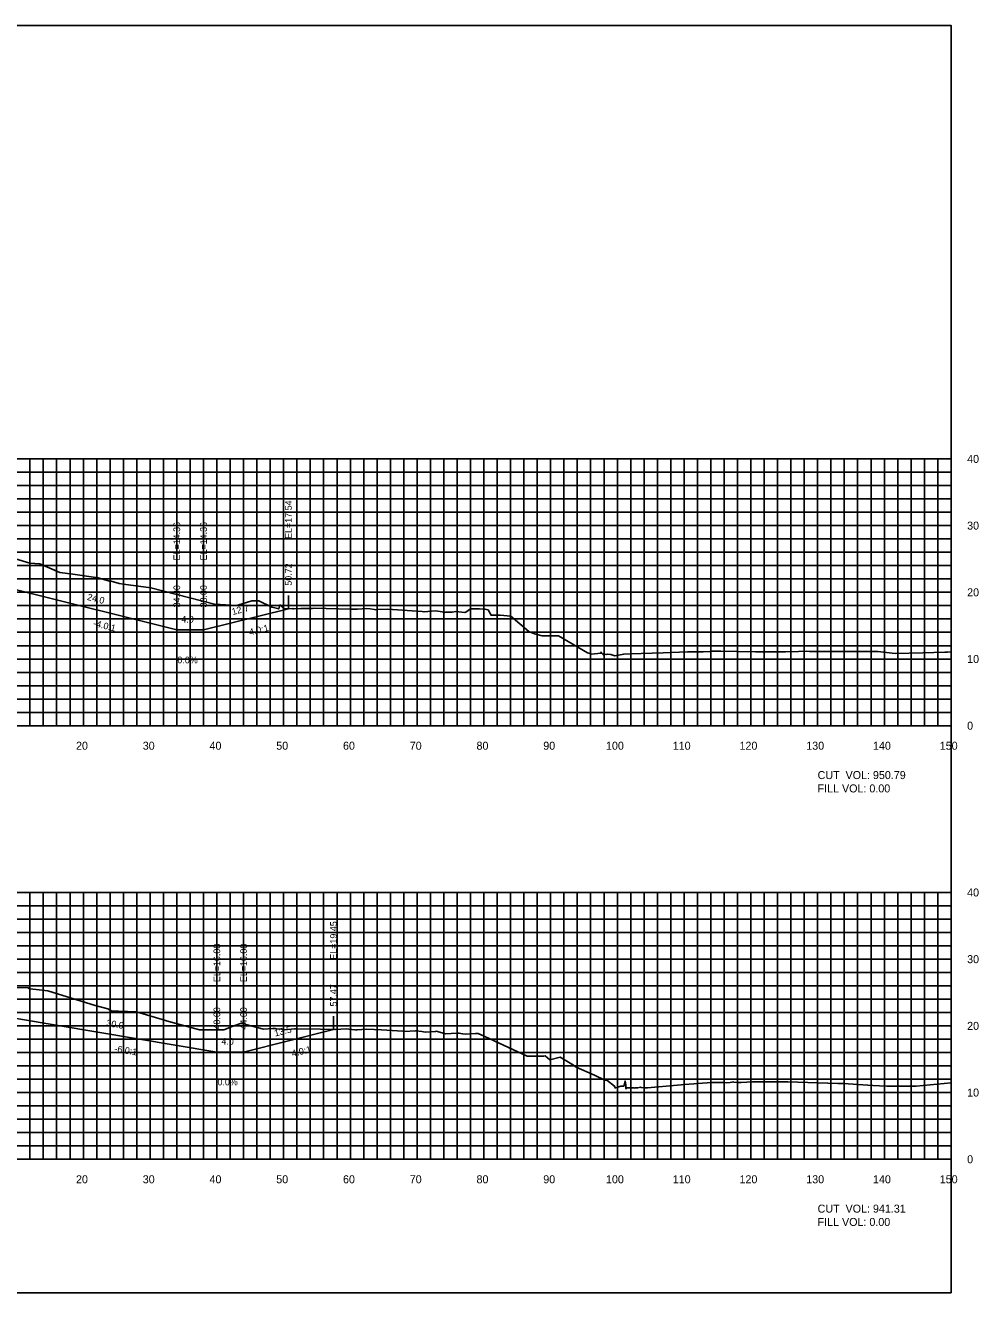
# Model space of a CAD drawing. Extents: x 1800976 to 1805104, y 250057 to 250580.
# Drawn here: x 1803322.3 to 1803465.1, y 250079.4 to 250269.4 of the extents above; entities that cross this region are included whole.
import ezdxf

# ---------------------------------------------------------------- set-up
doc = ezdxf.new("R2010")
doc.units = 0
for name, color, linetype in [('10', 7, 'Continuous'), ('3', 7, 'Continuous'), ('31', 7, 'Continuous'), ('4', 7, 'Continuous'), ('60', 7, 'Continuous'), ('ANNO-TXT', 7, 'Continuous'), ('CL-CNST', 7, 'Continuous'), ('Level 62', 7, 'Continuous'), ('M-ROADS', 7, 'Continuous')]:
    doc.layers.add(name, color=color, linetype=linetype)

msp = doc.modelspace()

# ---------------------------------------------------------------- linework, layer by layer
for p, q in [((1803361.72, 250181.97), (1803361.72, 250183.97)), ((1803345, 250178.79), (1803345, 250180.79)), ((1803349, 250178.79), (1803349, 250180.79)), ((1803368.47, 250118.88), (1803368.47, 250120.88)), ((1803351, 250115.51), (1803351, 250117.51)), ((1803355, 250115.51), (1803355, 250117.51))]:
    msp.add_line(p, q)
msp.add_lwpolyline([(1803161, 250079.43), (1803461, 250079.43), (1803461, 250269.43), (1803161, 250269.43)], close=True)
at = {"layer": '60'}
for p, q in [((1803461, 250164.43), (1803461, 250204.43)), ((1803461.06, 250204.43), (1803461, 250204.43)), ((1803461.06, 250194.43), (1803461, 250194.43)), ((1803461.06, 250184.43), (1803461, 250184.43)), ((1803461.06, 250174.43), (1803461, 250174.43)), ((1803161, 250164.43), (1803461, 250164.43)), ((1803331, 250164.37), (1803331, 250164.43)), ((1803341, 250164.37), (1803341, 250164.43)), ((1803351, 250164.37), (1803351, 250164.43)), ((1803361, 250164.37), (1803361, 250164.43)), ((1803371, 250164.37), (1803371, 250164.43)), ((1803381, 250164.37), (1803381, 250164.43)), ((1803391, 250164.37), (1803391, 250164.43)), ((1803401, 250164.37), (1803401, 250164.43)), ((1803411, 250164.37), (1803411, 250164.43)), ((1803421, 250164.37), (1803421, 250164.43)), ((1803431, 250164.37), (1803431, 250164.43)), ((1803441, 250164.37), (1803441, 250164.43)), ((1803451, 250164.37), (1803451, 250164.43)), ((1803461, 250164.37), (1803461, 250164.43)), ((1803461.06, 250164.43), (1803461, 250164.43)), ((1803461, 250099.43), (1803461, 250139.43)), ((1803461.06, 250139.43), (1803461, 250139.43)), ((1803461.06, 250129.43), (1803461, 250129.43)), ((1803461.06, 250119.43), (1803461, 250119.43)), ((1803461.06, 250109.43), (1803461, 250109.43)), ((1803161, 250099.43), (1803461, 250099.43)), ((1803331, 250099.37), (1803331, 250099.43)), ((1803341, 250099.37), (1803341, 250099.43)), ((1803351, 250099.37), (1803351, 250099.43)), ((1803361, 250099.37), (1803361, 250099.43)), ((1803371, 250099.37), (1803371, 250099.43)), ((1803381, 250099.37), (1803381, 250099.43)), ((1803391, 250099.37), (1803391, 250099.43)), ((1803401, 250099.37), (1803401, 250099.43)), ((1803411, 250099.37), (1803411, 250099.43)), ((1803421, 250099.37), (1803421, 250099.43)), ((1803431, 250099.37), (1803431, 250099.43)), ((1803441, 250099.37), (1803441, 250099.43)), ((1803451, 250099.37), (1803451, 250099.43)), ((1803461, 250099.37), (1803461, 250099.43)), ((1803461.06, 250099.43), (1803461, 250099.43))]:
    msp.add_line(p, q, dxfattribs=at)
at = {"layer": 'CL-CNST'}
for points in [[(1803267.75, 250186.14), (1803275, 250185.98), (1803311, 250185.19), (1803319, 250184.87), (1803321, 250184.79), (1803345, 250178.79), (1803349, 250178.79), (1803361.72, 250181.97)], [(1803268.63, 250120.34), (1803274.63, 250121.34), (1803276.67, 250121.42), (1803280.67, 250121.58), (1803311, 250120.91), (1803319, 250120.59), (1803321, 250120.51), (1803351, 250115.51), (1803355, 250115.51), (1803368.47, 250118.88)]]:
    msp.add_lwpolyline(points, dxfattribs=at)
at = {"layer": 'Level 62'}
for p, q in [((1803161, 250204.43), (1803461, 250204.43)), ((1803323, 250164.43), (1803323, 250204.43)), ((1803325, 250164.43), (1803325, 250204.43)), ((1803327, 250164.43), (1803327, 250204.43)), ((1803329, 250164.43), (1803329, 250204.43)), ((1803331, 250164.43), (1803331, 250204.43)), ((1803333, 250164.43), (1803333, 250204.43)), ((1803335, 250164.43), (1803335, 250204.43)), ((1803337, 250164.43), (1803337, 250204.43)), ((1803339, 250164.43), (1803339, 250204.43)), ((1803341, 250164.43), (1803341, 250204.43)), ((1803343, 250164.43), (1803343, 250204.43)), ((1803345, 250164.43), (1803345, 250204.43)), ((1803347, 250164.43), (1803347, 250204.43)), ((1803349, 250164.43), (1803349, 250204.43)), ((1803351, 250164.43), (1803351, 250204.43)), ((1803353, 250164.43), (1803353, 250204.43)), ((1803355, 250164.43), (1803355, 250204.43)), ((1803357, 250164.43), (1803357, 250204.43)), ((1803359, 250164.43), (1803359, 250204.43)), ((1803361, 250164.43), (1803361, 250204.43)), ((1803363, 250164.43), (1803363, 250204.43)), ((1803365, 250164.43), (1803365, 250204.43)), ((1803367, 250164.43), (1803367, 250204.43)), ((1803369, 250164.43), (1803369, 250204.43)), ((1803371, 250164.43), (1803371, 250204.43)), ((1803373, 250164.43), (1803373, 250204.43)), ((1803375, 250164.43), (1803375, 250204.43)), ((1803377, 250164.43), (1803377, 250204.43)), ((1803379, 250164.43), (1803379, 250204.43)), ((1803381, 250164.43), (1803381, 250204.43)), ((1803383, 250164.43), (1803383, 250204.43)), ((1803385, 250164.43), (1803385, 250204.43)), ((1803387, 250164.43), (1803387, 250204.43)), ((1803389, 250164.43), (1803389, 250204.43)), ((1803391, 250164.43), (1803391, 250204.43)), ((1803393, 250164.43), (1803393, 250204.43)), ((1803395, 250164.43), (1803395, 250204.43)), ((1803397, 250164.43), (1803397, 250204.43)), ((1803399, 250164.43), (1803399, 250204.43)), ((1803401, 250164.43), (1803401, 250204.43)), ((1803403, 250164.43), (1803403, 250204.43)), ((1803405, 250164.43), (1803405, 250204.43)), ((1803407, 250164.43), (1803407, 250204.43)), ((1803409, 250164.43), (1803409, 250204.43)), ((1803411, 250164.43), (1803411, 250204.43)), ((1803413, 250164.43), (1803413, 250204.43)), ((1803415, 250164.43), (1803415, 250204.43)), ((1803417, 250164.43), (1803417, 250204.43)), ((1803419, 250164.43), (1803419, 250204.43)), ((1803421, 250164.43), (1803421, 250204.43)), ((1803423, 250164.43), (1803423, 250204.43)), ((1803425, 250164.43), (1803425, 250204.43)), ((1803427, 250164.43), (1803427, 250204.43)), ((1803429, 250164.43), (1803429, 250204.43)), ((1803431, 250164.43), (1803431, 250204.43)), ((1803433, 250164.43), (1803433, 250204.43)), ((1803435, 250164.43), (1803435, 250204.43)), ((1803437, 250164.43), (1803437, 250204.43)), ((1803439, 250164.43), (1803439, 250204.43)), ((1803441, 250164.43), (1803441, 250204.43)), ((1803443, 250164.43), (1803443, 250204.43)), ((1803445, 250164.43), (1803445, 250204.43)), ((1803447, 250164.43), (1803447, 250204.43)), ((1803449, 250164.43), (1803449, 250204.43)), ((1803451, 250164.43), (1803451, 250204.43)), ((1803453, 250164.43), (1803453, 250204.43)), ((1803455, 250164.43), (1803455, 250204.43)), ((1803457, 250164.43), (1803457, 250204.43)), ((1803459, 250164.43), (1803459, 250204.43)), ((1803461, 250164.43), (1803461, 250204.43)), ((1803161, 250202.43), (1803461, 250202.43)), ((1803161, 250200.43), (1803461, 250200.43)), ((1803161, 250198.43), (1803461, 250198.43)), ((1803161, 250196.43), (1803461, 250196.43)), ((1803161, 250194.43), (1803461, 250194.43)), ((1803161, 250192.43), (1803461, 250192.43)), ((1803161, 250190.43), (1803461, 250190.43)), ((1803161, 250188.43), (1803461, 250188.43)), ((1803161, 250186.43), (1803461, 250186.43)), ((1803161, 250184.43), (1803461, 250184.43)), ((1803161, 250182.43), (1803461, 250182.43)), ((1803161, 250180.43), (1803461, 250180.43)), ((1803161, 250178.43), (1803461, 250178.43)), ((1803161, 250176.43), (1803461, 250176.43)), ((1803161, 250174.43), (1803461, 250174.43)), ((1803161, 250172.43), (1803461, 250172.43)), ((1803161, 250170.43), (1803461, 250170.43)), ((1803161, 250168.43), (1803461, 250168.43)), ((1803161, 250166.43), (1803461, 250166.43)), ((1803161, 250164.43), (1803461, 250164.43)), ((1803161, 250139.43), (1803461, 250139.43)), ((1803323, 250099.43), (1803323, 250139.43)), ((1803325, 250099.43), (1803325, 250139.43)), ((1803327, 250099.43), (1803327, 250139.43)), ((1803329, 250099.43), (1803329, 250139.43)), ((1803331, 250099.43), (1803331, 250139.43)), ((1803333, 250099.43), (1803333, 250139.43)), ((1803335, 250099.43), (1803335, 250139.43)), ((1803337, 250099.43), (1803337, 250139.43)), ((1803339, 250099.43), (1803339, 250139.43)), ((1803341, 250099.43), (1803341, 250139.43)), ((1803343, 250099.43), (1803343, 250139.43)), ((1803345, 250099.43), (1803345, 250139.43)), ((1803347, 250099.43), (1803347, 250139.43)), ((1803349, 250099.43), (1803349, 250139.43)), ((1803351, 250099.43), (1803351, 250139.43)), ((1803353, 250099.43), (1803353, 250139.43)), ((1803355, 250099.43), (1803355, 250139.43)), ((1803357, 250099.43), (1803357, 250139.43)), ((1803359, 250099.43), (1803359, 250139.43)), ((1803361, 250099.43), (1803361, 250139.43)), ((1803363, 250099.43), (1803363, 250139.43)), ((1803365, 250099.43), (1803365, 250139.43)), ((1803367, 250099.43), (1803367, 250139.43)), ((1803369, 250099.43), (1803369, 250139.43)), ((1803371, 250099.43), (1803371, 250139.43)), ((1803373, 250099.43), (1803373, 250139.43)), ((1803375, 250099.43), (1803375, 250139.43)), ((1803377, 250099.43), (1803377, 250139.43)), ((1803379, 250099.43), (1803379, 250139.43)), ((1803381, 250099.43), (1803381, 250139.43)), ((1803383, 250099.43), (1803383, 250139.43)), ((1803385, 250099.43), (1803385, 250139.43)), ((1803387, 250099.43), (1803387, 250139.43)), ((1803389, 250099.43), (1803389, 250139.43)), ((1803391, 250099.43), (1803391, 250139.43)), ((1803393, 250099.43), (1803393, 250139.43)), ((1803395, 250099.43), (1803395, 250139.43)), ((1803397, 250099.43), (1803397, 250139.43)), ((1803399, 250099.43), (1803399, 250139.43)), ((1803401, 250099.43), (1803401, 250139.43)), ((1803403, 250099.43), (1803403, 250139.43)), ((1803405, 250099.43), (1803405, 250139.43)), ((1803407, 250099.43), (1803407, 250139.43)), ((1803409, 250099.43), (1803409, 250139.43)), ((1803411, 250099.43), (1803411, 250139.43)), ((1803413, 250099.43), (1803413, 250139.43)), ((1803415, 250099.43), (1803415, 250139.43)), ((1803417, 250099.43), (1803417, 250139.43)), ((1803419, 250099.43), (1803419, 250139.43)), ((1803421, 250099.43), (1803421, 250139.43)), ((1803423, 250099.43), (1803423, 250139.43)), ((1803425, 250099.43), (1803425, 250139.43)), ((1803427, 250099.43), (1803427, 250139.43)), ((1803429, 250099.43), (1803429, 250139.43)), ((1803431, 250099.43), (1803431, 250139.43)), ((1803433, 250099.43), (1803433, 250139.43)), ((1803435, 250099.43), (1803435, 250139.43)), ((1803437, 250099.43), (1803437, 250139.43)), ((1803439, 250099.43), (1803439, 250139.43)), ((1803441, 250099.43), (1803441, 250139.43)), ((1803443, 250099.43), (1803443, 250139.43)), ((1803445, 250099.43), (1803445, 250139.43)), ((1803447, 250099.43), (1803447, 250139.43)), ((1803449, 250099.43), (1803449, 250139.43)), ((1803451, 250099.43), (1803451, 250139.43)), ((1803453, 250099.43), (1803453, 250139.43)), ((1803455, 250099.43), (1803455, 250139.43)), ((1803457, 250099.43), (1803457, 250139.43)), ((1803459, 250099.43), (1803459, 250139.43)), ((1803461, 250099.43), (1803461, 250139.43)), ((1803161, 250137.43), (1803461, 250137.43)), ((1803161, 250135.43), (1803461, 250135.43)), ((1803161, 250133.43), (1803461, 250133.43)), ((1803161, 250131.43), (1803461, 250131.43)), ((1803161, 250129.43), (1803461, 250129.43)), ((1803161, 250127.43), (1803461, 250127.43)), ((1803161, 250125.43), (1803461, 250125.43)), ((1803161, 250123.43), (1803461, 250123.43)), ((1803161, 250121.43), (1803461, 250121.43)), ((1803161, 250119.43), (1803461, 250119.43)), ((1803161, 250117.43), (1803461, 250117.43)), ((1803161, 250115.43), (1803461, 250115.43)), ((1803161, 250113.43), (1803461, 250113.43)), ((1803161, 250111.43), (1803461, 250111.43)), ((1803161, 250109.43), (1803461, 250109.43)), ((1803161, 250107.43), (1803461, 250107.43)), ((1803161, 250105.43), (1803461, 250105.43)), ((1803161, 250103.43), (1803461, 250103.43)), ((1803161, 250101.43), (1803461, 250101.43)), ((1803161, 250099.43), (1803461, 250099.43))]:
    msp.add_line(p, q, dxfattribs=at)
at = {"layer": 'M-ROADS'}
for points in [[(1803318.15, 250190.26), (1803322.96, 250188.79), (1803324.49, 250188.69), (1803327.48, 250187.42), (1803329.4, 250187.14), (1803333.23, 250186.59), (1803334.91, 250186.09), (1803335.19, 250186.08), (1803336.36, 250185.75), (1803337.01, 250185.66), (1803341.12, 250185.11), (1803350.64, 250182.63), (1803353.97, 250182.47), (1803354.12, 250182.5), (1803356.23, 250183.17), (1803357.3, 250183.17), (1803359.22, 250182.22), (1803359.71, 250182.08), (1803360.28, 250181.95), (1803360.43, 250182.54), (1803361.1, 250182), (1803362.28, 250181.94), (1803362.37, 250181.98), (1803362.47, 250181.94), (1803363.57, 250181.98), (1803364.05, 250181.98), (1803364.47, 250181.99), (1803365.31, 250182.02), (1803365.57, 250182.06), (1803371.04, 250181.89), (1803371.73, 250181.88), (1803372.07, 250181.9), (1803373.46, 250182.02), (1803373.97, 250181.93), (1803374.6, 250181.84), (1803374.82, 250181.81), (1803375.09, 250181.83), (1803376.55, 250181.92), (1803381.77, 250181.53), (1803382.02, 250181.51), (1803382.08, 250181.51), (1803383.69, 250181.64), (1803384.09, 250181.58), (1803385.1, 250181.43), (1803385.18, 250181.42), (1803385.18, 250181.42), (1803385.26, 250181.43), (1803386.24, 250181.44), (1803386.82, 250181.56), (1803388.15, 250181.41), (1803388.29, 250181.43), (1803388.99, 250181.96), (1803390.37, 250181.96), (1803391.15, 250181.91), (1803391.63, 250181.82), (1803392.09, 250181), (1803393.42, 250181), (1803395.03, 250180.84), (1803397.72, 250178.56), (1803398.61, 250178.19), (1803399.76, 250177.92), (1803401.12, 250177.92), (1803402.17, 250177.93), (1803406.51, 250175.36), (1803406.75, 250175.31), (1803407.11, 250175.16), (1803408.53, 250175.29), (1803408.56, 250175.46), (1803408.59, 250175.33), (1803408.77, 250175.28), (1803408.97, 250175.01), (1803409.02, 250175.02), (1803409.03, 250175.03), (1803409.1, 250175.13), (1803409.1, 250175.14), (1803409.31, 250175.09), (1803409.51, 250175.16), (1803409.53, 250175.16), (1803410, 250175.12), (1803410.6, 250174.92), (1803411.97, 250175.16), (1803412.92, 250175.2), (1803417.86, 250175.38), (1803421.51, 250175.51), (1803422.09, 250175.52), (1803423.86, 250175.52), (1803424.87, 250175.54), (1803425.06, 250175.6), (1803425.15, 250175.62), (1803425.18, 250175.61), (1803426.51, 250175.62), (1803431.7, 250175.53), (1803434.52, 250175.5), (1803436.18, 250175.51), (1803438.12, 250175.55), (1803439.35, 250175.59), (1803439.79, 250175.58), (1803440.99, 250175.58), (1803443.63, 250175.54), (1803450.02, 250175.54), (1803452.6, 250175.27), (1803456.75, 250175.35), (1803460.04, 250175.48), (1803460.45, 250175.48), (1803461, 250175.49)], [(1803320.71, 250125.19), (1803322.71, 250125.11), (1803322.92, 250124.99), (1803323.94, 250124.87), (1803325.67, 250124.66), (1803332.76, 250122.47), (1803334.68, 250122), (1803335.27, 250121.61), (1803335.66, 250121.61), (1803336.27, 250121.61), (1803338.94, 250121.51), (1803343.83, 250120.1), (1803348.38, 250118.86), (1803348.6, 250118.86), (1803351.02, 250118.84), (1803352.06, 250118.84), (1803353.7, 250119.5), (1803354.52, 250119.78), (1803354.77, 250119.78), (1803355.15, 250119.78), (1803355.32, 250119.63), (1803357.97, 250118.93), (1803359.41, 250119.02), (1803359.69, 250119.04), (1803359.76, 250119.03), (1803359.9, 250119.01), (1803360.68, 250118.92), (1803361.07, 250118.85), (1803362.63, 250118.98), (1803362.79, 250118.99), (1803366.55, 250118.92), (1803368.68, 250118.87), (1803368.78, 250118.88), (1803370.39, 250118.99), (1803370.79, 250118.93), (1803371.66, 250118.83), (1803371.76, 250118.82), (1803371.8, 250118.81), (1803371.97, 250118.83), (1803373.49, 250118.92), (1803375.68, 250118.85), (1803378.87, 250118.65), (1803379.11, 250118.58), (1803380.76, 250118.69), (1803380.81, 250118.69), (1803380.85, 250118.69), (1803381.72, 250118.57), (1803382.21, 250118.51), (1803383.75, 250118.61), (1803383.92, 250118.62), (1803384.05, 250118.58), (1803385.24, 250118.26), (1803386.96, 250118.34), (1803387.18, 250118.35), (1803387.31, 250118.33), (1803387.81, 250118.26), (1803388.2, 250118.19), (1803389.75, 250118.28), (1803390.14, 250118.3), (1803391.17, 250117.82), (1803397.49, 250114.91), (1803399.1, 250114.9), (1803399.91, 250114.89), (1803399.99, 250114.9), (1803400.2, 250114.92), (1803400.86, 250114.35), (1803402.45, 250114.74), (1803404.42, 250113.55), (1803404.85, 250113.25), (1803407.57, 250112.03), (1803409.12, 250111.28), (1803409.42, 250111.28), (1803410.55, 250110.39), (1803410.65, 250110.13), (1803410.7, 250110.13), (1803410.76, 250110.13), (1803410.99, 250110.17), (1803411.22, 250110.31), (1803411.54, 250110.38), (1803411.86, 250110.39), (1803411.87, 250110.39), (1803411.91, 250110.38), (1803411.95, 250110.34), (1803412.16, 250111.17), (1803412.26, 250110.54), (1803412.29, 250110.14), (1803412.29, 250110.13), (1803412.3, 250109.97), (1803412.3, 250110.11), (1803412.34, 250110.16), (1803412.46, 250110.14), (1803412.46, 250110.14), (1803412.49, 250110.12), (1803412.5, 250110.13), (1803412.74, 250110.13), (1803413.43, 250110.13), (1803413.56, 250110.11), (1803413.64, 250110.13), (1803414.06, 250110.13), (1803414.47, 250110.24), (1803414.59, 250110.21), (1803415.09, 250110.13), (1803415.14, 250110.12), (1803415.37, 250110.13), (1803415.51, 250110.13), (1803421.13, 250110.63), (1803425.09, 250110.92), (1803426.78, 250110.92), (1803426.88, 250110.92), (1803427.32, 250110.9), (1803427.88, 250110.93), (1803428.15, 250110.98), (1803428.41, 250111.03), (1803428.46, 250110.99), (1803428.93, 250110.92), (1803429.33, 250110.92), (1803429.54, 250110.93), (1803431.27, 250111.05), (1803433.65, 250111.05), (1803435.15, 250111.05), (1803436.56, 250111.05), (1803444.04, 250110.8), (1803444.85, 250110.78), (1803449.28, 250110.48), (1803450.26, 250110.44), (1803451.37, 250110.39), (1803453.15, 250110.39), (1803454.85, 250110.39), (1803455.55, 250110.39), (1803455.69, 250110.39), (1803455.77, 250110.4), (1803461, 250110.88)]]:
    msp.add_lwpolyline(points, dxfattribs=at)

# ---------------------------------------------------------------- texts
for s, rotation, p in [('-4.0:1', 345.9638, (1803332.4, 250179.36)), ('4.0:1', 14.0362, (1803355.97, 250177.95)), ('-6.0:1', 350.5377, (1803335.59, 250115.55)), ('4.0:1', 14.0362, (1803362.34, 250114.77))]:
    msp.add_text(s, height=1, rotation=rotation).set_placement(p)
at = {"layer": '10'}
for s, p in [('20', (1803329.9, 250160.83)), ('30', (1803339.9, 250160.83)), ('40', (1803349.9, 250160.83)), ('50', (1803359.9, 250160.83)), ('60', (1803369.9, 250160.83)), ('70', (1803379.9, 250160.83)), ('80', (1803389.9, 250160.83)), ('90', (1803399.9, 250160.83)), ('100', (1803409.3, 250160.83)), ('110', (1803419.3, 250160.83)), ('120', (1803429.3, 250160.83)), ('130', (1803439.3, 250160.83)), ('140', (1803449.3, 250160.83)), ('150', (1803459.3, 250160.83)), ('20', (1803329.9, 250095.83)), ('30', (1803339.9, 250095.83)), ('40', (1803349.9, 250095.83)), ('50', (1803359.9, 250095.83)), ('60', (1803369.9, 250095.83)), ('70', (1803379.9, 250095.83)), ('80', (1803389.9, 250095.83)), ('90', (1803399.9, 250095.83)), ('100', (1803409.3, 250095.83)), ('110', (1803419.3, 250095.83)), ('120', (1803429.3, 250095.83)), ('130', (1803439.3, 250095.83)), ('140', (1803449.3, 250095.83)), ('150', (1803459.3, 250095.83))]:
    msp.add_text(s, height=1.2, dxfattribs=at).set_placement(p)
at = {"layer": '3'}
for s, p in [('EL=17.54', (1803362.22, 250192.44)), ('EL=14.36', (1803345.5, 250189.21)), ('EL=14.36', (1803349.5, 250189.21)), ('50.72', (1803362.22, 250185.42)), ('34.00', (1803345.5, 250182.16)), ('38.00', (1803349.5, 250182.16)), ('EL=19.45', (1803368.97, 250129.35)), ('EL=16.08', (1803351.5, 250125.98)), ('EL=16.08', (1803355.5, 250125.98)), ('57.47', (1803368.97, 250122.33)), ('40.00', (1803351.5, 250118.88)), ('44.00', (1803355.5, 250118.88))]:
    msp.add_text(s, height=1, rotation=90, dxfattribs=at).set_placement(p)
at = {"layer": '31'}
for s, p in [('40', (1803463.4, 250203.83)), ('30', (1803463.4, 250193.83)), ('20', (1803463.4, 250183.83)), ('10', (1803463.4, 250173.83)), ('0', (1803463.4, 250163.83)), ('40', (1803463.4, 250138.83)), ('30', (1803463.4, 250128.83)), ('20', (1803463.4, 250118.83)), ('10', (1803463.4, 250108.83)), ('0', (1803463.4, 250098.83))]:
    msp.add_text(s, height=1.2, dxfattribs=at).set_placement(p)
at = {"layer": '4'}
for s, rotation, p in [('24.0', 345.9638, (1803331.5, 250183.3)), ('12.7', 14.0362, (1803353.37, 250181.02)), ('30.0', 350.5377, (1803334.39, 250119.4)), ('13.5', 14.0362, (1803359.74, 250117.83))]:
    msp.add_text(s, height=1, rotation=rotation, dxfattribs=at).set_placement(p)
for s, p in [('4.0', (1803345.68, 250179.89)), ('0.0%', (1803345.09, 250173.79)), ('4.0', (1803351.68, 250116.61)), ('0.0%', (1803351.09, 250110.51))]:
    msp.add_text(s, height=1, dxfattribs=at).set_placement(p)
at = {"layer": 'ANNO-TXT'}
for s, p in [('CUT  VOL: 950.79', (1803441, 250156.43)), ('FILL VOL: 0.00', (1803441, 250154.43)), ('CUT  VOL: 941.31', (1803441, 250091.43)), ('FILL VOL: 0.00', (1803441, 250089.43))]:
    msp.add_text(s, height=1.2, dxfattribs=at).set_placement(p)

doc.saveas('drawing.dxf')
